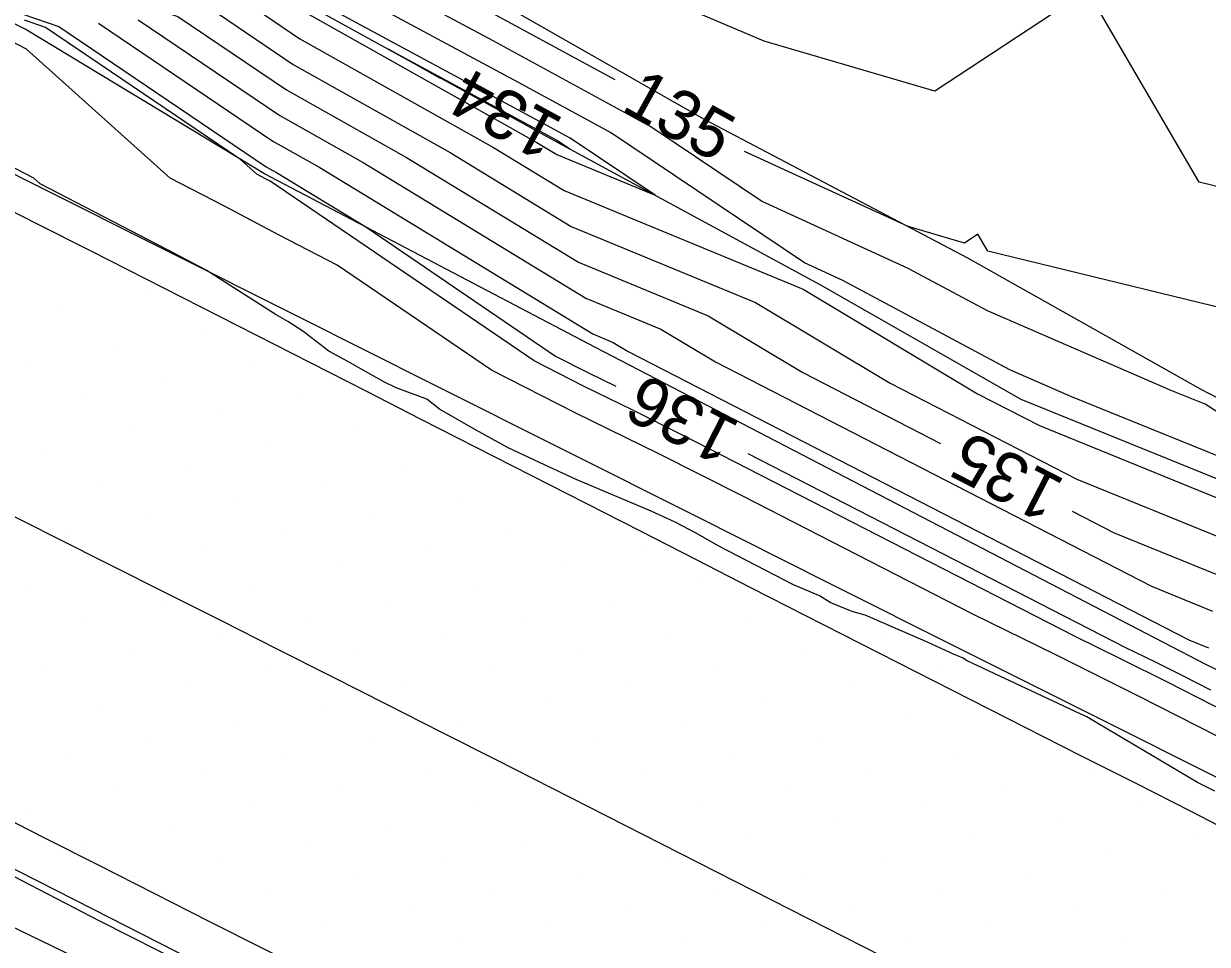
# Model space of a CAD drawing. Extents: x 2354170 to 2357230, y 866100 to 868290.
# Drawn here: x 2354344.76 to 2354392.71, y 867866.67 to 867903.96 of the extents above; entities that cross this region are included whole.
import ezdxf

# ---------------------------------------------------------------- set-up
doc = ezdxf.new("R2010")
doc.units = 0
for name, color, linetype in [('Default', 7, 'Continuous'), ('DTM Contours Major', 7, 'Continuous'), ('DTM Contours Major Text', 7, 'Continuous'), ('DTM Contours Minor', 7, 'Continuous'), ('DTM Contours Minor Text', 7, 'Continuous'), ('Exist DTM Breakline', 7, 'Continuous'), ('Exist DTM Scan Elevation Point', 7, 'Continuous'), ('Exist Roads EOP', 7, 'Continuous'), ('PH Exist DTM Breakline', 7, 'Continuous')]:
    doc.layers.add(name, color=color, linetype=linetype)

msp = doc.modelspace()

# ---------------------------------------------------------------- linework, layer by layer
at = {"layer": 'Default'}
for points in [[(2354368.718, 867901.692), (2354362.742, 867904.946), (2354361.297, 867905.726), (2354341.937, 867916.947), (2354341.755, 867917.065), (2354341.683, 867917.1), (2354334.57, 867920.472), (2354333.855, 867920.813), (2354323.299, 867926.261), (2354321.497, 867927.354), (2354320.795, 867927.62), (2354312.658, 867932.386), (2354309.273, 867934.035), (2354299.278, 867938.847), (2354297.335, 867939.858)], [(2354294.306, 867933.747), (2354299.612, 867930.841), (2354311.251, 867923.546), (2354312.579, 867922.222), (2354313.757, 867921.395), (2354314.79, 867921.351), (2354317.27, 867920.912), (2354320.14, 867920.221), (2354326.315, 867917.679), (2354331.575, 867914.888), (2354337.864, 867911.816), (2354344.317, 867908.598), (2354355.826, 867904.66), (2354356.229, 867904.388), (2354365.552, 867899.151), (2354366.366, 867898.655), (2354370.343, 867897.01), (2354366.899, 867899.324), (2354365.84, 867899.901), (2354357.394, 867904.458)], [(2354293.335, 867931.787), (2354305.096, 867925.346), (2354308.841, 867922.998), (2354311.152, 867920.695), (2354313.202, 867919.256), (2354315, 867919.18), (2354315.946, 867919.013), (2354321.286, 867917.727), (2354324.617, 867916.356), (2354327.455, 867914.85), (2354340.917, 867908.274), (2354344.542, 867906.466), (2354351.008, 867904.254), (2354355.409, 867901.275), (2354360.276, 867898.542), (2354367.238, 867894.296), (2354372.49, 867892.125), (2354376.327, 867889.825), (2354381.894, 867886.961)], [(2354397.4, 867896.316), (2354392.372, 867897.543), (2354387.849, 867905.308), (2354381.677, 867901.223), (2354374.764, 867903.257), (2354366.28, 867906.856)], [(2354400.008, 867883.795), (2354392.616, 867888.545), (2354391.273, 867889.091), (2354383.806, 867892.322), (2354380.595, 867894.045), (2354374.654, 867896.77), (2354370.162, 867899.787), (2354363.775, 867903.264), (2354359.787, 867905.416)], [(2354393.218, 867886.411), (2354387.182, 867888.864), (2354384.709, 867889.933), (2354377.945, 867893.562), (2354376.396, 867894.272), (2354368.53, 867899.556), (2354364.808, 867901.582), (2354358.278, 867905.105)], [(2354344.767, 867904.334), (2354346.19, 867903.848), (2354354.59, 867898.163), (2354355, 867897.933), (2354358.62, 867895.725), (2354366.302, 867890.491), (2354367.61, 867889.826), (2354368.745, 867889.271)], [(2354352.614, 867904.39), (2354355.683, 867902.313), (2354362.034, 867898.745), (2354366.947, 867895.749), (2354374.411, 867892.663), (2354379.866, 867889.395), (2354387.42, 867885.508), (2354393.262, 867883.135)], [(2354354.22, 867904.525), (2354355.956, 867903.35), (2354363.793, 867898.948), (2354366.657, 867897.202), (2354376.333, 867893.202), (2354383.405, 867888.964), (2354385.906, 867887.677), (2354393.432, 867884.62)], [(2354393.154, 867875.073), (2354389.887, 867876.739), (2354386.598, 867878.375), (2354383.215, 867880.041), (2354373.889, 867884.824), (2354370.495, 867886.535), (2354367.104, 867888.194), (2354363.707, 867889.922), (2354357.463, 867894.177), (2354355.115, 867895.391), (2354352.866, 867896.586), (2354350.7, 867897.709), (2354344.877, 867902.93), (2354344.199, 867903.281), (2354343.487, 867903.618), (2354342.76, 867903.97)], [(2354347.796, 867903.983), (2354354.863, 867899.201), (2354356.759, 867898.136), (2354367.819, 867891.39), (2354368.646, 867891.048), (2354369.25, 867890.686), (2354391.962, 867879), (2354392.752, 867878.679)], [(2354349.402, 867904.119), (2354355.136, 867900.238), (2354358.517, 867898.339), (2354367.529, 867892.843), (2354370.568, 867891.587), (2354372.789, 867890.256), (2354390.448, 867881.169), (2354392.922, 867880.165)], [(2354393.017, 867872.874), (2354392.309, 867873.227), (2354388.301, 867875.601), (2354388.035, 867875.756), (2354387.821, 867875.887), (2354387.558, 867876.005), (2354382.984, 867878.147), (2354382.797, 867878.267), (2354382.459, 867878.402), (2354381.397, 867878.894), (2354378.85, 867880), (2354378.357, 867880.134), (2354377.776, 867880.369), (2354377.433, 867880.508), (2354377.004, 867880.789), (2354375.951, 867881.224), (2354372.927, 867882.8), (2354371.999, 867883.323), (2354371.149, 867883.769), (2354370.18, 867884.217), (2354367.138, 867885.494), (2354365.862, 867886.088), (2354364.391, 867886.782), (2354363.072, 867887.508), (2354361.605, 867888.35), (2354361.093, 867888.747), (2354359.857, 867889.203), (2354359.351, 867889.448), (2354357.893, 867890.279), (2354357.127, 867890.698), (2354356.067, 867891.501), (2354355.468, 867891.891), (2354354.993, 867892.173), (2354352.156, 867893.97), (2354350.588, 867894.803), (2354345.43, 867897.477), (2354345.176, 867897.705), (2354340.086, 867900.341)], [(2354387.229, 867884.216), (2354388.934, 867883.339), (2354393.092, 867881.65), (2354397.689, 867879.123), (2354400.577, 867877.597), (2354410.966, 867872.886), (2354417.643, 867869.721), (2354420.559, 867868.358), (2354422.016, 867869.274), (2354423.197, 867871.497), (2354423.174, 867873.637), (2354418.054, 867876.041), (2354414.601, 867877.82), (2354405.415, 867882.185), (2354405.01, 867882.399), (2354404.35, 867882.752), (2354402.508, 867883.935), (2354394.508, 867892.138), (2354383.814, 867894.75), (2354383.416, 867895.432), (2354382.875, 867895.073), (2354380.591, 867895.745), (2354373.959, 867898.787)], [(2354374.09, 867886.545), (2354389.391, 867878.697), (2354390.565, 867878.119), (2354391.706, 867877.552), (2354392.839, 867876.974)], [(2354309.877, 867884.787), (2354330.849, 867873.915), (2354331.305, 867873.681), (2354331.741, 867873.47), (2354332.195, 867873.244), (2354332.649, 867873.014), (2354347.612, 867865.779), (2354349.215, 867864.952), (2354350.788, 867864.153), (2354352.35, 867863.352), (2354360.569, 867859.885), (2354363.099, 867858.589), (2354365.633, 867857.309), (2354374.193, 867851.627), (2354375.396, 867851.039), (2354376.654, 867850.422), (2354377.985, 867849.78), (2354387.732, 867844.922), (2354390.202, 867843.712), (2354392.727, 867842.47)], [(2354319.207, 867882.048), (2354322.277, 867880.457), (2354327.031, 867878.021), (2354331.564, 867875.818), (2354336.296, 867873.469), (2354341.02, 867871.076), (2354342.932, 867870.152), (2354347.83, 867867.625), (2354352.639, 867865.184), (2354357.414, 867862.736), (2354358.625, 867862.225), (2354363.552, 867859.702), (2354368.484, 867857.21), (2354369.768, 867856.358), (2354374.471, 867854.063), (2354379.388, 867851.647), (2354384.588, 867849.14), (2354385.24, 867848.814), (2354390.415, 867846.28), (2354395.703, 867843.68)]]:
    msp.add_lwpolyline(points, dxfattribs=at)
at = {"layer": 'DTM Contours Major'}
for points in [[(2354368.718, 867901.692), (2354362.742, 867904.946), (2354361.297, 867905.726), (2354341.937, 867916.947), (2354341.755, 867917.065), (2354341.683, 867917.1), (2354334.57, 867920.472), (2354333.855, 867920.813), (2354323.299, 867926.261), (2354321.497, 867927.354), (2354320.795, 867927.62), (2354312.658, 867932.386), (2354309.273, 867934.035), (2354299.278, 867938.847), (2354297.335, 867939.858)], [(2354293.335, 867931.787), (2354305.096, 867925.346), (2354308.841, 867922.998), (2354311.152, 867920.695), (2354313.202, 867919.256), (2354315, 867919.18), (2354315.946, 867919.013), (2354321.286, 867917.727), (2354324.617, 867916.356), (2354327.455, 867914.85), (2354340.917, 867908.274), (2354344.542, 867906.466), (2354351.008, 867904.254), (2354355.409, 867901.275), (2354360.276, 867898.542), (2354367.238, 867894.296), (2354372.49, 867892.125), (2354376.327, 867889.825), (2354381.894, 867886.961)], [(2354387.229, 867884.216), (2354388.934, 867883.339), (2354393.092, 867881.65), (2354397.689, 867879.123), (2354400.577, 867877.597), (2354410.966, 867872.886), (2354417.643, 867869.721), (2354420.559, 867868.358), (2354422.016, 867869.274), (2354423.197, 867871.497), (2354423.174, 867873.637), (2354418.054, 867876.041), (2354414.601, 867877.82), (2354405.415, 867882.185), (2354405.01, 867882.399), (2354404.35, 867882.752), (2354402.508, 867883.935), (2354394.508, 867892.138), (2354383.814, 867894.75), (2354383.416, 867895.432), (2354382.875, 867895.073), (2354380.591, 867895.745), (2354373.959, 867898.787)]]:
    msp.add_lwpolyline(points, dxfattribs=at)
at = {"layer": 'DTM Contours Minor'}
for points in [[(2354397.708, 867874.115), (2354394.812, 867875.401), (2354392.944, 867876.34), (2354391.1, 867877.281), (2354389.242, 867878.204), (2354387.332, 867879.145), (2354371.446, 867887.293), (2354369.442, 867888.303), (2354367.441, 867889.282), (2354365.437, 867890.302), (2354354.747, 867897.585), (2354354.562, 867897.681), (2354354.384, 867897.775), (2354354.213, 867897.863), (2354353.544, 867898.463), (2354345.655, 867903.803), (2354344.793, 867904.098)], [(2354359.538, 867902.926), (2354366.184, 867899.34), (2354366.355, 867899.247), (2354366.911, 867898.873), (2354366.91, 867898.874)], [(2354361.646, 867901.742), (2354359.538, 867902.926)]]:
    msp.add_lwpolyline(points, dxfattribs=at)
at = {"layer": 'Exist DTM Breakline'}
for points in [[(2354394.274, 867870.906), (2354392.048, 867872.044), (2354389.82, 867873.178), (2354387.59, 867874.309), (2354385.361, 867875.441), (2354383.132, 867876.572), (2354380.904, 867877.707), (2354378.677, 867878.842), (2354376.45, 867879.978), (2354374.223, 867881.114), (2354371.996, 867882.25), (2354369.769, 867883.386), (2354367.542, 867884.522), (2354365.315, 867885.658), (2354363.088, 867886.795), (2354360.861, 867887.931), (2354358.635, 867889.068), (2354356.408, 867890.204), (2354354.18, 867891.339), (2354351.952, 867892.472), (2354349.724, 867893.605), (2354347.495, 867894.739), (2354345.266, 867895.87), (2354343.036, 867897)], [(2354343.829, 867884.276), (2354346.062, 867883.153), (2354348.295, 867882.029), (2354350.528, 867880.904), (2354352.76, 867879.778), (2354354.992, 867878.651), (2354357.223, 867877.524), (2354359.454, 867876.396), (2354361.685, 867875.266), (2354363.915, 867874.136), (2354366.144, 867873.006), (2354368.374, 867871.874), (2354370.602, 867870.742), (2354372.831, 867869.608), (2354375.059, 867868.475), (2354377.287, 867867.34), (2354379.514, 867866.205), (2354381.742, 867865.07), (2354383.969, 867863.935), (2354386.197, 867862.8), (2354388.424, 867861.665), (2354390.652, 867860.531), (2354392.88, 867859.397)], [(2354394.72, 867846.264), (2354392.484, 867847.382), (2354390.248, 867848.5), (2354388.012, 867849.618), (2354385.777, 867850.737), (2354383.541, 867851.856), (2354381.306, 867852.976), (2354379.071, 867854.096), (2354376.836, 867855.217), (2354374.602, 867856.339), (2354372.368, 867857.461), (2354370.134, 867858.584), (2354367.901, 867859.707), (2354365.668, 867860.831), (2354363.436, 867861.956), (2354361.203, 867863.082), (2354358.972, 867864.209), (2354356.74, 867865.337), (2354354.51, 867866.465), (2354352.279, 867867.594), (2354350.049, 867868.724), (2354347.819, 867869.855), (2354345.59, 867870.986), (2354343.361, 867872.118)]]:
    msp.add_lwpolyline(points, dxfattribs=at)
at = {"layer": 'Exist DTM Scan Elevation Point'}
for p, q in [((2354345.682, 867895.757), (2354345.682, 867895.757)), ((2354347.767, 867894.377), (2354347.767, 867894.377)), ((2354349.852, 867892.998), (2354349.852, 867892.998)), ((2354346.388, 867892.292), (2354346.388, 867892.292)), ((2354351.937, 867891.618), (2354351.937, 867891.618)), ((2354348.473, 867890.913), (2354348.473, 867890.913)), ((2354357.487, 867890.944), (2354357.487, 867890.944)), ((2354345.008, 867890.207), (2354345.008, 867890.207)), ((2354354.022, 867890.239), (2354354.022, 867890.239)), ((2354350.558, 867889.533), (2354350.558, 867889.533)), ((2354359.572, 867889.565), (2354359.572, 867889.565)), ((2354356.107, 867888.859), (2354356.107, 867888.859)), ((2354347.093, 867888.828), (2354347.093, 867888.828)), ((2354352.643, 867888.154), (2354352.643, 867888.154)), ((2354361.657, 867888.186), (2354361.657, 867888.186)), ((2354349.178, 867887.448), (2354349.178, 867887.448)), ((2354358.192, 867887.48), (2354358.192, 867887.48)), ((2354345.714, 867886.743), (2354345.714, 867886.743)), ((2354354.728, 867886.774), (2354354.728, 867886.774)), ((2354363.742, 867886.806), (2354363.742, 867886.806)), ((2354351.263, 867886.069), (2354351.263, 867886.069)), ((2354360.277, 867886.101), (2354360.277, 867886.101)), ((2354347.799, 867885.363), (2354347.799, 867885.363)), ((2354356.813, 867885.395), (2354356.813, 867885.395)), ((2354353.348, 867884.689), (2354353.348, 867884.689)), ((2354362.362, 867884.721), (2354362.362, 867884.721)), ((2354349.884, 867883.984), (2354349.884, 867883.984)), ((2354358.898, 867884.016), (2354358.898, 867884.016)), ((2354367.912, 867884.047), (2354367.912, 867884.047)), ((2354346.42, 867883.278), (2354346.42, 867883.278)), ((2354355.433, 867883.31), (2354355.433, 867883.31)), ((2354364.447, 867883.342), (2354364.447, 867883.342)), ((2354360.983, 867882.636), (2354360.983, 867882.636)), ((2354369.997, 867882.668), (2354369.997, 867882.668)), ((2354351.969, 867882.604), (2354351.969, 867882.604)), ((2354357.518, 867881.931), (2354357.518, 867881.931)), ((2354366.532, 867881.962), (2354366.532, 867881.962)), ((2354345.04, 867881.193), (2354345.04, 867881.193)), ((2354354.054, 867881.225), (2354354.054, 867881.225)), ((2354363.068, 867881.257), (2354363.068, 867881.257)), ((2354372.082, 867881.288), (2354372.082, 867881.288)), ((2354350.589, 867880.519), (2354350.589, 867880.519)), ((2354359.603, 867880.551), (2354359.603, 867880.551)), ((2354368.617, 867880.583), (2354368.617, 867880.583)), ((2354377.631, 867880.614), (2354377.631, 867880.614)), ((2354347.125, 867879.814), (2354347.125, 867879.814)), ((2354356.139, 867879.846), (2354356.139, 867879.846)), ((2354365.153, 867879.877), (2354365.153, 867879.877)), ((2354374.167, 867879.909), (2354374.167, 867879.909)), ((2354352.674, 867879.14), (2354352.674, 867879.14)), ((2354361.688, 867879.172), (2354361.688, 867879.172)), ((2354370.702, 867879.203), (2354370.702, 867879.203)), ((2354379.716, 867879.235), (2354379.716, 867879.235)), ((2354349.21, 867878.434), (2354349.21, 867878.434)), ((2354358.224, 867878.466), (2354358.224, 867878.466)), ((2354367.238, 867878.498), (2354367.238, 867878.498)), ((2354376.252, 867878.53), (2354376.252, 867878.53)), ((2354381.801, 867877.856), (2354381.801, 867877.856)), ((2354345.746, 867877.729), (2354345.746, 867877.729)), ((2354354.759, 867877.761), (2354354.759, 867877.761)), ((2354363.773, 867877.792), (2354363.773, 867877.792)), ((2354372.787, 867877.824), (2354372.787, 867877.824)), ((2354351.295, 867877.055), (2354351.295, 867877.055)), ((2354360.309, 867877.087), (2354360.309, 867877.087)), ((2354369.323, 867877.118), (2354369.323, 867877.118)), ((2354378.337, 867877.15), (2354378.337, 867877.15)), ((2354365.858, 867876.413), (2354365.858, 867876.413)), ((2354374.872, 867876.445), (2354374.872, 867876.445)), ((2354383.886, 867876.476), (2354383.886, 867876.476)), ((2354347.831, 867876.349), (2354347.831, 867876.349)), ((2354356.844, 867876.381), (2354356.844, 867876.381)), ((2354353.38, 867875.676), (2354353.38, 867875.676)), ((2354362.394, 867875.707), (2354362.394, 867875.707)), ((2354371.408, 867875.739), (2354371.408, 867875.739)), ((2354380.422, 867875.771), (2354380.422, 867875.771)), ((2354349.916, 867874.97), (2354349.916, 867874.97)), ((2354358.929, 867875.002), (2354358.929, 867875.002)), ((2354367.943, 867875.033), (2354367.943, 867875.033)), ((2354376.957, 867875.065), (2354376.957, 867875.065)), ((2354346.451, 867874.265), (2354346.451, 867874.265)), ((2354355.465, 867874.296), (2354355.465, 867874.296)), ((2354364.479, 867874.328), (2354364.479, 867874.328)), ((2354373.493, 867874.36), (2354373.493, 867874.36)), ((2354382.506, 867874.391), (2354382.506, 867874.391)), ((2354352.001, 867873.591), (2354352.001, 867873.591)), ((2354361.014, 867873.622), (2354361.014, 867873.622)), ((2354370.028, 867873.654), (2354370.028, 867873.654)), ((2354379.042, 867873.686), (2354379.042, 867873.686)), ((2354388.056, 867873.717), (2354388.056, 867873.717)), ((2354348.536, 867872.885), (2354348.536, 867872.885)), ((2354357.55, 867872.917), (2354357.55, 867872.917)), ((2354366.564, 867872.948), (2354366.564, 867872.948)), ((2354375.578, 867872.98), (2354375.578, 867872.98)), ((2354384.591, 867873.012), (2354384.591, 867873.012)), ((2354345.072, 867872.18), (2354345.072, 867872.18)), ((2354354.086, 867872.211), (2354354.086, 867872.211)), ((2354363.099, 867872.243), (2354363.099, 867872.243)), ((2354372.113, 867872.275), (2354372.113, 867872.275)), ((2354381.127, 867872.306), (2354381.127, 867872.306)), ((2354390.141, 867872.338), (2354390.141, 867872.338)), ((2354377.663, 867871.601), (2354377.663, 867871.601)), ((2354386.676, 867871.632), (2354386.676, 867871.632)), ((2354350.621, 867871.506), (2354350.621, 867871.506)), ((2354359.635, 867871.537), (2354359.635, 867871.537)), ((2354368.649, 867871.569), (2354368.649, 867871.569)), ((2354347.157, 867870.8), (2354347.157, 867870.8)), ((2354356.171, 867870.832), (2354356.171, 867870.832)), ((2354365.184, 867870.863), (2354365.184, 867870.863)), ((2354374.198, 867870.895), (2354374.198, 867870.895)), ((2354383.212, 867870.927), (2354383.212, 867870.927)), ((2354392.226, 867870.958), (2354392.226, 867870.958)), ((2354361.72, 867870.158), (2354361.72, 867870.158)), ((2354370.734, 867870.19), (2354370.734, 867870.19)), ((2354379.748, 867870.221), (2354379.748, 867870.221)), ((2354388.761, 867870.253), (2354388.761, 867870.253)), ((2354352.706, 867870.126), (2354352.706, 867870.126)), ((2354349.242, 867869.421), (2354349.242, 867869.421)), ((2354358.256, 867869.452), (2354358.256, 867869.452)), ((2354367.269, 867869.484), (2354367.269, 867869.484)), ((2354376.283, 867869.516), (2354376.283, 867869.516)), ((2354385.297, 867869.547), (2354385.297, 867869.547)), ((2354354.791, 867868.747), (2354354.791, 867868.747)), ((2354363.805, 867868.778), (2354363.805, 867868.778)), ((2354372.819, 867868.81), (2354372.819, 867868.81)), ((2354381.833, 867868.842), (2354381.833, 867868.842)), ((2354390.846, 867868.873), (2354390.846, 867868.873)), ((2354360.341, 867868.073), (2354360.341, 867868.073)), ((2354369.354, 867868.105), (2354369.354, 867868.105)), ((2354378.368, 867868.136), (2354378.368, 867868.136)), ((2354387.382, 867868.168), (2354387.382, 867868.168)), ((2354356.876, 867867.367), (2354356.876, 867867.367)), ((2354365.89, 867867.399), (2354365.89, 867867.399)), ((2354374.904, 867867.431), (2354374.904, 867867.431)), ((2354383.918, 867867.462), (2354383.918, 867867.462)), ((2354362.426, 867866.693), (2354362.426, 867866.693)), ((2354371.439, 867866.725), (2354371.439, 867866.725)), ((2354380.453, 867866.757), (2354380.453, 867866.757)), ((2354389.467, 867866.789), (2354389.467, 867866.789))]:
    msp.add_line(p, q, dxfattribs=at)
at = {"layer": 'Exist Roads EOP'}
for points in [[(2354329.098, 867905.531), (2354334.463, 867902.845), (2354339.827, 867900.157), (2354345.19, 867897.466), (2354350.553, 867894.775), (2354355.915, 867892.083), (2354361.277, 867889.39), (2354366.638, 867886.698), (2354372.001, 867884.005), (2354377.363, 867881.314), (2354382.726, 867878.624), (2354388.091, 867875.936), (2354393.455, 867873.25)], [(2354395.789, 867843.715), (2354390.425, 867846.403), (2354385.062, 867849.094), (2354379.7, 867851.787), (2354374.342, 867854.486), (2354368.987, 867857.193), (2354363.636, 867859.908), (2354358.289, 867862.63), (2354352.943, 867865.354), (2354347.596, 867868.076), (2354342.246, 867870.792), (2354336.893, 867873.501), (2354331.535, 867876.201), (2354326.172, 867878.893), (2354320.807, 867881.579), (2354315.44, 867884.26), (2354310.071, 867886.939), (2354304.702, 867889.618), (2354299.333, 867892.296), (2354293.965, 867894.977), (2354288.599, 867897.662), (2354283.238, 867900.355), (2354279.71, 867902.135)]]:
    msp.add_lwpolyline(points, dxfattribs=at)
at = {"layer": 'PH Exist DTM Breakline'}
for points in [[(2354295.105, 867935.358), (2354314.507, 867924.286), (2354318.808, 867923.119), (2354327.669, 867918.735), (2354335.188, 867914.921), (2354344.113, 867910.534), (2354356.312, 867904.701), (2354366.251, 867899.232), (2354377.011, 867893.392), (2354385.156, 867888.751), (2354393.516, 867885.355), (2354402.856, 867880.296), (2354408.718, 867877.199), (2354421.172, 867871.054)], [(2354362.155, 867905.902), (2354372.334, 867900.095), (2354382.99, 867894.481), (2354392.444, 867889.156), (2354405.17, 867882.555), (2354416.797, 867878.051), (2354424.062, 867874.783), (2354424.013, 867871.675), (2354422.357, 867868.556), (2354420.175, 867866.672), (2354413.441, 867868.134), (2354392.672, 867877.983), (2354367.928, 867890.847), (2354354.514, 867897.877), (2354344.831, 867903.733), (2354322.628, 867914.805)]]:
    msp.add_lwpolyline(points, dxfattribs=at)

# ---------------------------------------------------------------- texts
at = {"layer": 'Default'}
for s, rotation, p in [('135', 330.9952, (2354368.906, 867900.471)), ('136', 152.9797, (2354373.874, 867887.785)), ('135', 152.7725, (2354387.015, 867885.451))]:
    msp.add_text(s, height=2, rotation=rotation, dxfattribs=at).set_placement(p)
at = {"layer": 'DTM Contours Major Text'}
for rotation, p in [(330.9952, (2354368.906, 867900.471)), (152.7725, (2354387.015, 867885.451))]:
    msp.add_text('135', height=2, rotation=rotation, dxfattribs=at).set_placement(p)
at = {"layer": 'DTM Contours Minor Text'}
msp.add_text('134', height=2, rotation=151.4172, dxfattribs=at).set_placement((2354366.71, 867900.078))

doc.saveas('drawing.dxf')
